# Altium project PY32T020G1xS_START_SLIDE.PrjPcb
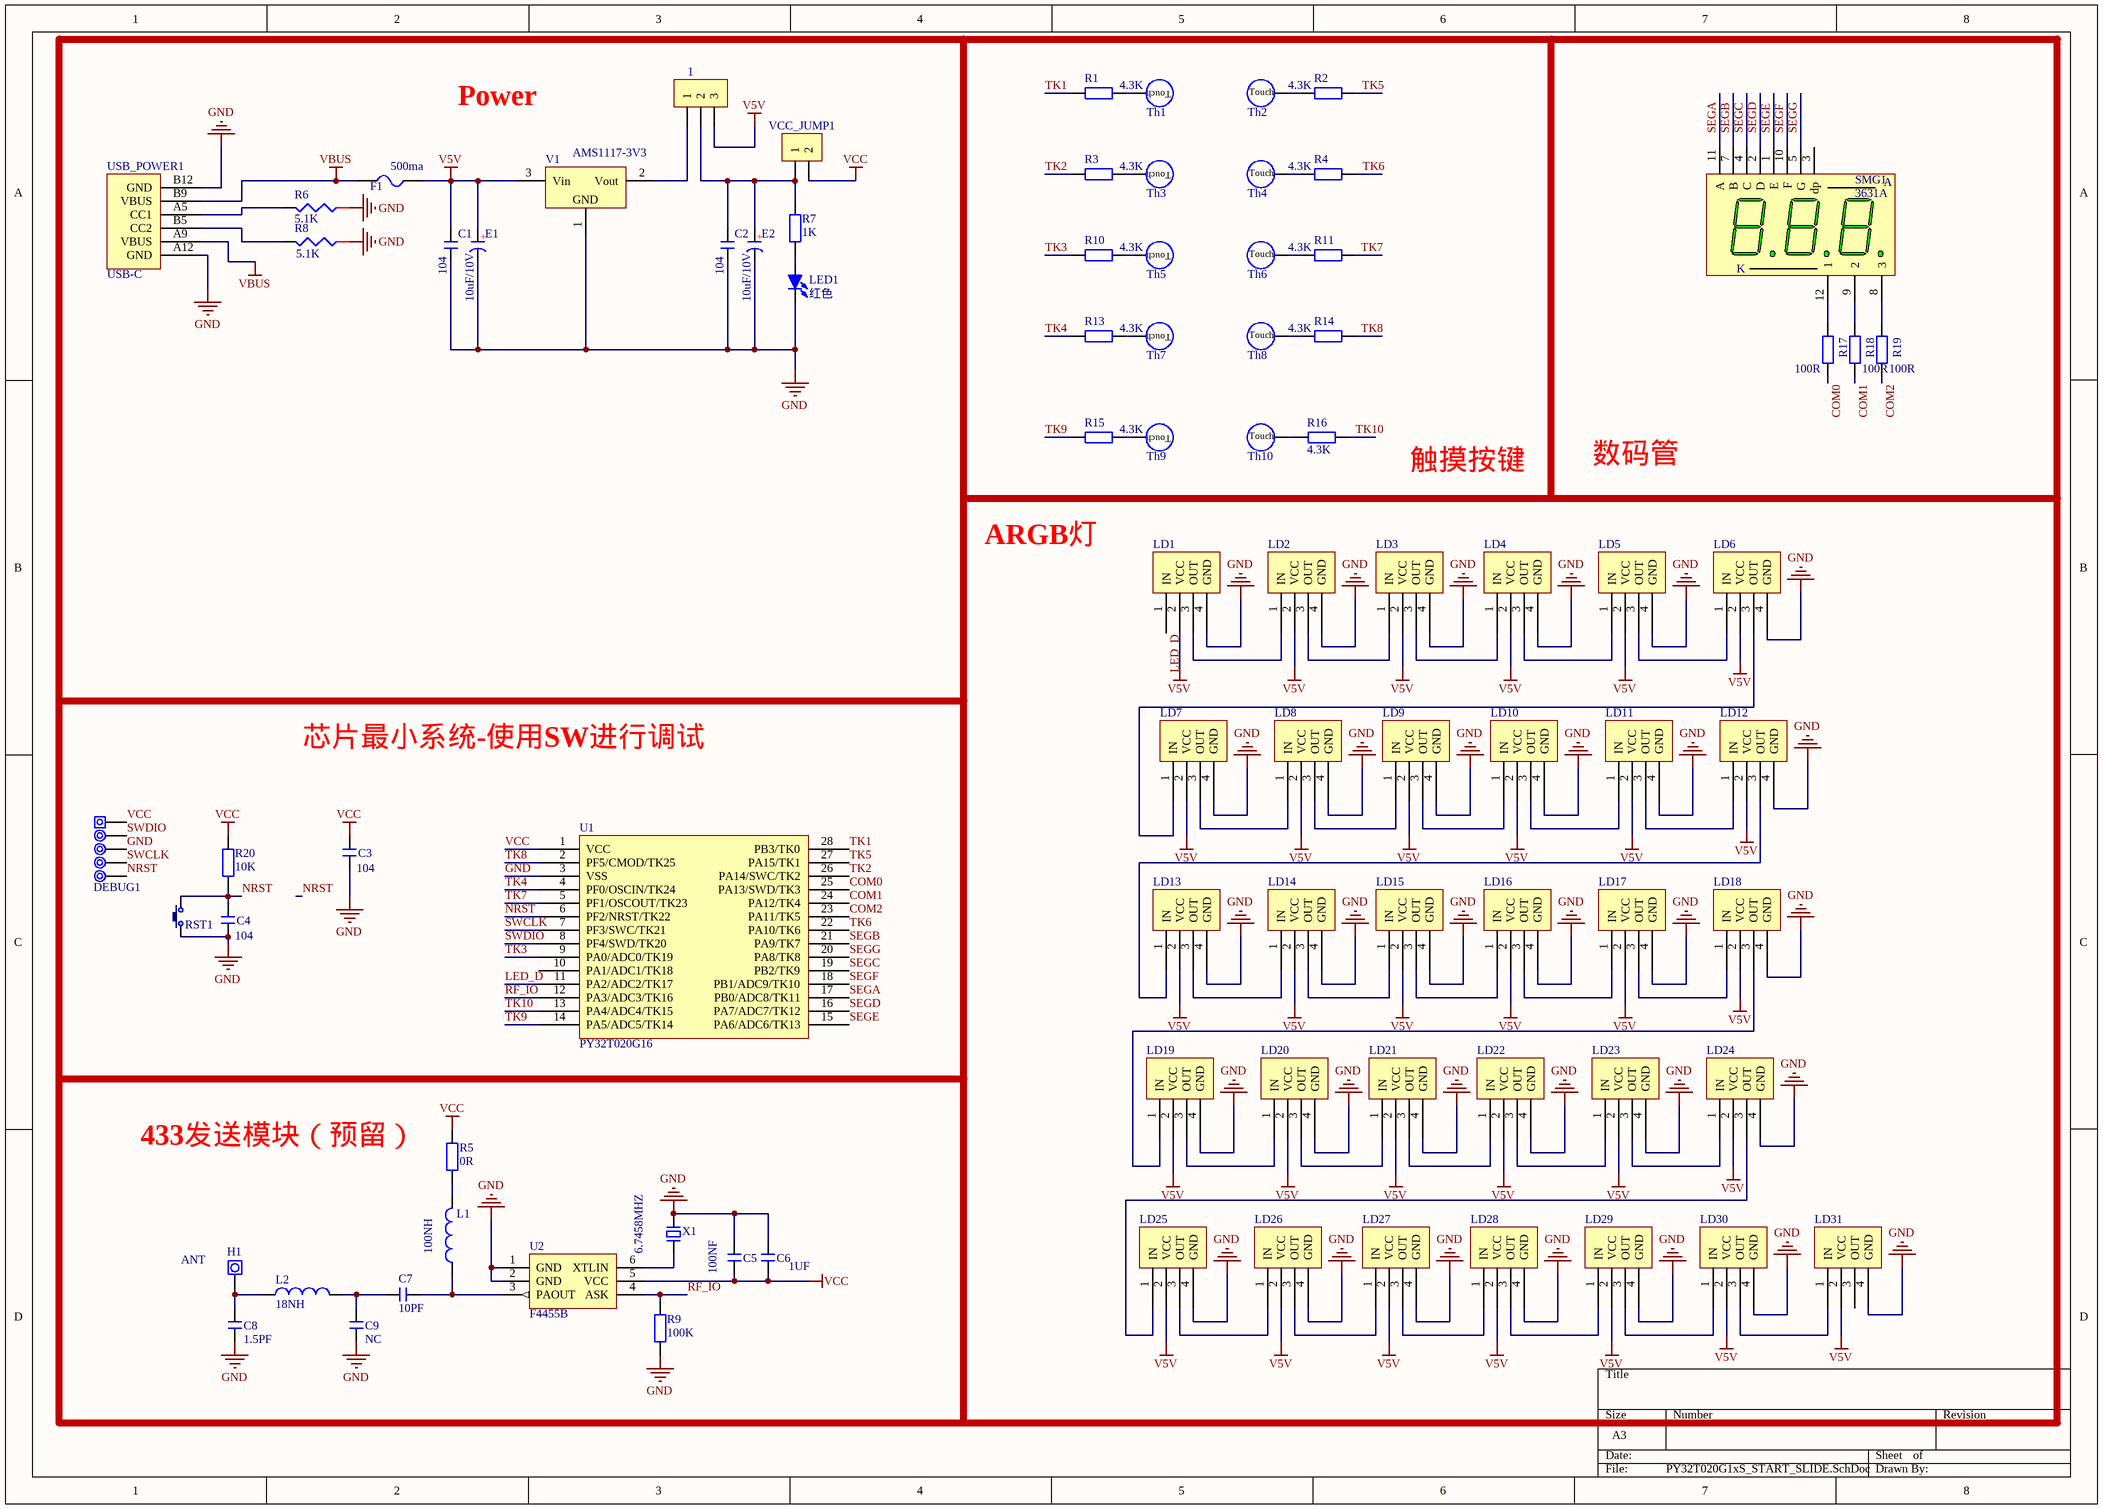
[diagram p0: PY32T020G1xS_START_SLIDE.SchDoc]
1 sheet, 86 parts. Net scope: global (net labels, ports and power ports of the same name join across sheets).
Board file: PY32T020G1xS_START_SLIDE.PcbDoc

## Sheet PY32T020G1xS_START_SLIDE.SchDoc
size A3

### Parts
1  HDR-1X3  [HDR2.54-LI-3P]  (value not drawn)
C1  104  [C 0603_L]
C2  104  [C 0603_L]
C3  104  [C 0603_L]
C4  104  [C 0603_L]
C5  100NF  [C 0603_M]
C6  1UF  [C 0603_M]
C7  10PF  [C 0603_M]
C8  1.5PF  [C 0603_M]
C9  NC  [C 0603_M]
DEBUG1  ISP  [ISP_DIP_2.54_5P]  (value not drawn)
E1  10uF/10V  [C 0805_L]
E2  10uF/10V  [C 0805_L]
F1  500ma  [FU 0805]
H1  ANT  [PAD1-B]
L1  100NH  [L 0603_L]
L2  18NH  [L 0603_L]
LD1  LED1  [LED4020]  (value not drawn)
LD2  LED1  [LED4020]  (value not drawn)
LD3  LED1  [LED4020]  (value not drawn)
LD4  LED1  [LED4020]  (value not drawn)
LD5  LED1  [LED4020]  (value not drawn)
LD6  LED1  [LED4020]  (value not drawn)
LD7  LED1  [LED4020]  (value not drawn)
LD8  LED1  [LED4020]  (value not drawn)
LD9  LED1  [LED4020]  (value not drawn)
LD10  LED1  [LED4020]  (value not drawn)
LD11  LED1  [LED4020]  (value not drawn)
LD12  LED1  [LED4020]  (value not drawn)
LD13  LED1  [LED4020]  (value not drawn)
LD14  LED1  [LED4020]  (value not drawn)
LD15  LED1  [LED4020]  (value not drawn)
LD16  LED1  [LED4020]  (value not drawn)
LD17  LED1  [LED4020]  (value not drawn)
LD18  LED1  [LED4020]  (value not drawn)
LD19  LED1  [LED4020]  (value not drawn)
LD20  LED1  [LED4020]  (value not drawn)
LD21  LED1  [LED4020]  (value not drawn)
LD22  LED1  [LED4020]  (value not drawn)
LD23  LED1  [LED4020]  (value not drawn)
LD24  LED1  [LED4020]  (value not drawn)
LD25  LED1  [LED4020]  (value not drawn)
LD26  LED1  [LED4020]  (value not drawn)
LD27  LED1  [LED4020]  (value not drawn)
LD28  LED1  [LED4020]  (value not drawn)
LD29  LED1  [LED4020]  (value not drawn)
LD30  LED1  [LED4020]  (value not drawn)
LD31  LED1  [LED4020]  (value not drawn)
LED1  红色  [LED 0805R]
R1  4.3K  [R 0603_L]
R2  4.3K  [R 0603_L]
R3  4.3K  [R 0603_L]
R4  4.3K  [R 0603_L]
R5  0R  [R 0603_M]
R6  5.1K  [R 0603_L]
R7  1K  [R 0603_L]
R8  5.1K  [R 0603_L]
R9  100K  [R 0603_M]
R10  4.3K  [R 0603_L]
R11  4.3K  [R 0603_L]
R13  4.3K  [R 0603_L]
R14  4.3K  [R 0603_L]
R15  4.3K  [R 0603_L]
R16  4.3K  [R 0603_L]
R17  100R  [R 0603_L]
R18  100R  [R 0603_L]
R19  100R  [R 0603_L]
R20  10K  [R 0603_L]
RST1  6x6x5  [TSW SMD-3*6*5]  (value not drawn)
SMG1  3631A  [SMG 0.36-3P]
Th1  Touch 10X10mm  [Touch-10X10mm]  (value not drawn)
Th2  Touch 10X10mm  [Touch-10X10mm]  (value not drawn)
Th3  Touch 10X10mm  [Touch-10X10mm]  (value not drawn)
Th4  Touch 10X10mm  [Touch-10X10mm]  (value not drawn)
Th5  Touch 10X10mm  [Touch-10X10mm]  (value not drawn)
Th6  Touch 10X10mm  [Touch-10X10mm]  (value not drawn)
Th7  Touch 10X10mm  [Touch-10X10mm]  (value not drawn)
Th8  Touch 10X10mm  [Touch-10X10mm]  (value not drawn)
Th9  Touch 10X10mm  [Touch-10X10mm]  (value not drawn)
Th10  Touch 10X10mm  [Touch-10X10mm]  (value not drawn)
U1  PY32T020G16  [SOP28_L]
U2  F4455B  [SOT23-6L]
USB_POWER1  USB-C  [USB-C/S_C]
V1  AMS1117-3V3  [SOT223_N]
VCC_JUMP1  HDR-1X2  [HDR2.54-LI-2P]  (value not drawn)
X1  6.7458MHZ  [OSC HC-49SMD]

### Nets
GND: C1.1 C2.1 C3.1 C4.1 C5.1 C6.1 C8.1 C9.1 DEBUG1.3 E1.2(K) E2.2(K) LD1.4(GND) LD2.4(GND) LD3.4(GND) LD4.4(GND) LD5.4(GND) LD6.4(GND) LD7.4(GND) LD8.4(GND) LD9.4(GND) LD10.4(GND) LD11.4(GND) LD12.4(GND) LD13.4(GND) LD14.4(GND) LD15.4(GND) LD16.4(GND) LD17.4(GND) LD18.4(GND) LD19.4(GND) LD20.4(GND) LD21.4(GND) LD22.4(GND) LD23.4(GND) LD24.4(GND) LD25.4(GND) LD26.4(GND) LD27.4(GND) LD28.4(GND) LD29.4(GND) LD30.4(GND) LD31.4(GND) LED1.2(K) R6.1 R8.1 R9.2 RST1.1 U1.3(VSS) U2.1(GND) U2.2(GND) USB_POWER1.A12(GND) USB_POWER1.B12(GND) V1.1(GND) X1.2
V5V: 1.3 C1.2 E1.1(A) F1.2 LD1.2(VCC) LD2.2(VCC) LD3.2(VCC) LD4.2(VCC) LD5.2(VCC) LD6.2(VCC) LD7.2(VCC) LD8.2(VCC) LD9.2(VCC) LD10.2(VCC) LD11.2(VCC) LD12.2(VCC) LD13.2(VCC) LD14.2(VCC) LD15.2(VCC) LD16.2(VCC) LD17.2(VCC) LD18.2(VCC) LD19.2(VCC) LD20.2(VCC) LD21.2(VCC) LD22.2(VCC) LD23.2(VCC) LD24.2(VCC) LD25.2(VCC) LD26.2(VCC) LD27.2(VCC) LD28.2(VCC) LD29.2(VCC) LD30.2(VCC) LD31.2(VCC) V1.3(Vin)
VBUS: F1.1 USB_POWER1.A9(VBUS) USB_POWER1.B9(VBUS)
VCC: C3.2 C5.2 C6.2 DEBUG1.1 R5.1 R20.2 U1.1(VCC) U2.5(VCC) VCC_JUMP1.2
COM0: R17.2 U1.25(PA13/SWD/TK3)
COM1: R18.2 U1.24(PA12/TK4)
COM2: R19.2 U1.23(PA11/TK5)
LED_D: LD1.1(IN) U1.11(PA2/ADC2/TK17)
NRST: C4.2 DEBUG1.5 R20.1 RST1.2 U1.6(PF2/NRST/TK22)
RF_IO: R9.1 U1.12(PA3/ADC3/TK16) U2.4(ASK)
SEGA: SMG1.11(A) U1.17(PB0/ADC8/TK11)
SEGB: SMG1.7(B) U1.21(PA9/TK7)
SEGC: SMG1.4(C) U1.19(PB2/TK9)
SEGD: SMG1.2(D) U1.16(PA7/ADC7/TK12)
SEGE: SMG1.1(E) U1.15(PA6/ADC6/TK13)
SEGF: SMG1.10(F) U1.18(PB1/ADC9/TK10)
SEGG: SMG1.5(G) U1.20(PA8/TK8)
SWCLK: DEBUG1.4 U1.7(PF3/SWC/TK21)
SWDIO: DEBUG1.2 U1.8(PF4/SWD/TK20)
TK1: R1.1 U1.28(PB3/TK0)
TK2: R3.1 U1.26(PA14/SWC/TK2)
TK3: R10.1 U1.9(PA0/ADC0/TK19)
TK4: R13.1 U1.4(PF0/OSCIN/TK24)
TK5: R2.1 U1.27(PA15/TK1)
TK6: R4.1 U1.22(PA10/TK6)
TK7: R11.1 U1.5(PF1/OSCOUT/TK23)
TK8: R14.1 U1.2(PF5/CMOD/TK25)
TK9: R15.1 U1.14(PA5/ADC5/TK14)
TK10: R16.1 U1.13(PA4/ADC4/TK15)
Net1_1: 1.1 V1.2(Vout)
Net1_2: 1.2 C2.2 E2.1(A) R7.2 VCC_JUMP1.1
NetC7_1: C7.1 L1.1 U2.3(PAOUT)
NetC7_2: C7.2 C9.2 L2.2
NetC8_2: C8.2 H1.1 L2.1
NetL1_2: L1.2 R5.2
NetLD1_3: LD1.3(OUT) LD2.1(IN)
NetLD2_3: LD2.3(OUT) LD3.1(IN)
NetLD3_3: LD3.3(OUT) LD4.1(IN)
NetLD4_3: LD4.3(OUT) LD5.1(IN)
NetLD5_3: LD5.3(OUT) LD6.1(IN)
NetLD6_3: LD6.3(OUT) LD7.1(IN)
NetLD7_3: LD7.3(OUT) LD8.1(IN)
NetLD8_3: LD8.3(OUT) LD9.1(IN)
NetLD9_3: LD9.3(OUT) LD10.1(IN)
NetLD10_3: LD10.3(OUT) LD11.1(IN)
NetLD11_3: LD11.3(OUT) LD12.1(IN)
NetLD12_3: LD12.3(OUT) LD13.1(IN)
NetLD13_3: LD13.3(OUT) LD14.1(IN)
NetLD14_3: LD14.3(OUT) LD15.1(IN)
NetLD15_3: LD15.3(OUT) LD16.1(IN)
NetLD16_3: LD16.3(OUT) LD17.1(IN)
NetLD17_3: LD17.3(OUT) LD18.1(IN)
NetLD18_3: LD18.3(OUT) LD19.1(IN)
NetLD19_3: LD19.3(OUT) LD20.1(IN)
NetLD20_3: LD20.3(OUT) LD21.1(IN)
NetLD21_3: LD21.3(OUT) LD22.1(IN)
NetLD22_3: LD22.3(OUT) LD23.1(IN)
NetLD23_3: LD23.3(OUT) LD24.1(IN)
NetLD24_3: LD24.3(OUT) LD25.1(IN)
NetLD25_3: LD25.3(OUT) LD26.1(IN)
NetLD26_3: LD26.3(OUT) LD27.1(IN)
NetLD27_3: LD27.3(OUT) LD28.1(IN)
NetLD28_3: LD28.3(OUT) LD29.1(IN)
NetLD29_3: LD29.3(OUT) LD30.1(IN)
NetLD30_3: LD30.3(OUT) LD31.1(IN)
NetLED1_1: LED1.1(A) R7.1
NetR1_2: R1.2 Th1.Touch
NetR2_2: R2.2 Th2.Touch
NetR3_2: R3.2 Th3.Touch
NetR4_2: R4.2 Th4.Touch
NetR6_2: R6.2 USB_POWER1.A5(CC1)
NetR8_2: R8.2 USB_POWER1.B5(CC2)
NetR10_2: R10.2 Th5.Touch
NetR11_2: R11.2 Th6.Touch
NetR13_2: R13.2 Th7.Touch
NetR14_2: R14.2 Th8.Touch
NetR15_2: R15.2 Th9.Touch
NetR16_2: R16.2 Th10.Touch
NetR17_1: R17.1 SMG1.12(1)
NetR18_1: R18.1 SMG1.9(2)
NetR19_1: R19.1 SMG1.8(3)
NetU2_6: U2.6(XTLIN) X1.1

Not connected (* = marked no-connect by the designer): LD31 3(OUT); SMG1 3(dp); U1 10(PA1/ADC1/TK18)

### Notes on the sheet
- Power
- 触摸按键
- 数码管
- ARGB灯
- 芯片最小系统-使用SW进行调试
- 433发送模块（预留）

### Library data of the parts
1 = Header 3: 3P接插件; 版权归属: 源创客
C1-C9 = C: 无极性贴片电容; 版权归属: 源创客; 材质: X7R
DEBUG1 = ISP_5Pin: 程序下载端口; 版权归属: 源创客
E1 E2 = C-CM: 贴片电解电容; 版权归属: 源创客
F1 = FU: 贴片保险丝; 版权归属: 源创客
H1 = PAD1: 引线焊盘; 版权归属: 源创客
L1 L2 = L: 小功率贴片电感; 版权归属: 源创客
LD1-LD31 = LED4020
LED1 = LED-SMD: 贴片LED; 版权归属: 源创客
R1-R5 R7 R9-R11 R13-R20 = R: 贴片电阻; 版权归属: 源创客
R6 R8 = R
RST1 = TSW DIP-2Pin-6x6: 2脚直插6x6轻触开关; BOM名称: 2脚轻触开关; 版权归属: 源创客
SMG1 = 3631A: 0.36寸3位共阴数码管; 版权归属: 源创客
Th1-Th10 = Touch-1P: 触控焊盘; 版权归属: 源创客
USB_POWER1 = USB-C_6P/S: USB-C_6P型母接口; BOM名称: USB-C型母接口; 版权归属: 源创客
V1 = AMS1117: 三端稳压芯片; BOM名称: 稳压芯片; 版权归属: 源创客
VCC_JUMP1 = Header 2: 2P接插件; 版权归属: 源创客
X1 = XTAL-2P: 2脚无源脚晶振; 版权归属: 源创客; 负载电容: CL20pF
